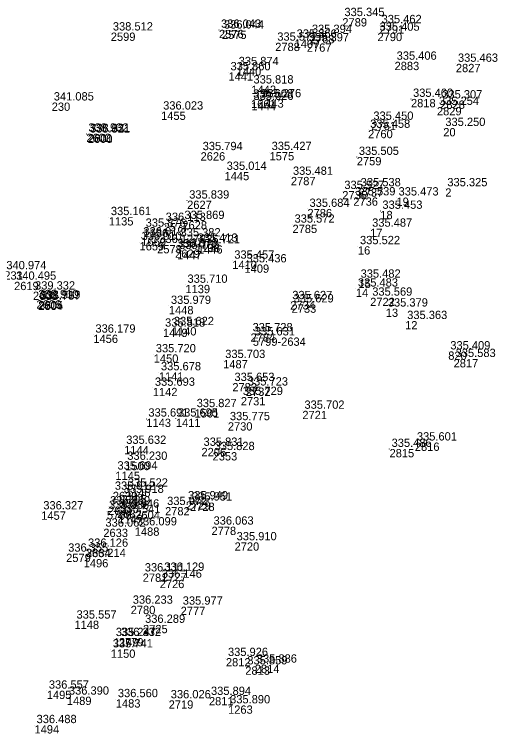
# Model space of a CAD drawing. Extents: x -829398 to -819400, y -1074439 to -1067977.
# Drawn here: x -819998.2 to -819929.2, y -1073325.7 to -1073221.6 of the extents above; entities that cross this region are included whole.
import ezdxf

# ---------------------------------------------------------------- set-up
doc = ezdxf.new("R2010")
doc.units = 0
for name, color, linetype in [('Vrstva 60', 7, 'Continuous'), ('Vrstva 61', 7, 'Continuous'), ('Čísla bodů_doměření_2012', 7, 'Continuous')]:
    doc.layers.add(name, color=color, linetype=linetype)

# ---------------------------------------------------------------- blocks, each defined once
blk = doc.blocks.new('BOD')
at = {"layer": 'Čísla bodů_doměření_2012'}
for p, q in [((-0.15, 0), (0.15, 0)), ((0, -0.15), (0, 0.15))]:
    blk.add_line(p, q, dxfattribs=at)

msp = doc.modelspace()

# ---------------------------------------------------------------- block references
at = {"layer": 'Vrstva 60', "xscale": 0.010000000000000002, "yscale": 0.010000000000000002}
for p in [(-819950.692, -1073222.135), (-819945.306, -1073223.158), (-819984.23, -1073224.218), (-819984.23, -1073224.218), (-819968.559, -1073223.823), (-819968.559, -1073223.823), (-819968.135, -1073223.939), (-819968.135, -1073223.939), (-819955.405, -1073224.574), (-819955.405, -1073224.574), (-819945.601, -1073224.25), (-819957.608, -1073225.257), (-819957.608, -1073225.257), (-819960.415, -1073225.694), (-819960.415, -1073225.694), (-819955.83, -1073225.792), (-819955.83, -1073225.792), (-819943.129, -1073228.449), (-819966.008, -1073229.234), (-819966.008, -1073229.234), (-819934.25, -1073228.748), (-819967.188, -1073229.98), (-819967.188, -1073229.98), (-819963.866, -1073231.888), (-819963.866, -1073231.888), (-819963.919, -1073233.941), (-819963.919, -1073233.941), (-819962.758, -1073233.88), (-819962.758, -1073233.88), (-819940.752, -1073233.821), (-819992.785, -1073234.345), (-819992.785, -1073234.345), (-819963.868, -1073234.268), (-819963.868, -1073234.268), (-819936.52, -1073234.049), (-819976.945, -1073235.658), (-819976.945, -1073235.658), (-819936.995, -1073234.992), (-819946.498, -1073237.14), (-819936.076, -1073238.036), (-819936.076, -1073238.036), (-819987.773, -1073238.853), (-819987.773, -1073238.853), (-819987.558, -1073238.989), (-819987.558, -1073238.989), (-819987.525, -1073238.907), (-819987.525, -1073238.907), (-819946.964, -1073238.306), (-819971.225, -1073241.531), (-819971.225, -1073241.531), (-819961.237, -1073241.513), (-819961.237, -1073241.513), (-819948.602, -1073242.224), (-819967.749, -1073244.384), (-819967.749, -1073244.384), (-819958.146, -1073245.103), (-819958.146, -1073245.103), (-819950.704, -1073247.152), (-819948.336, -1073246.762), (-819935.785, -1073246.762), (-819935.785, -1073246.762), (-819949.106, -1073248.075), (-819942.855, -1073248.093), (-819942.855, -1073248.093), (-819973.173, -1073248.54), (-819973.173, -1073248.54), (-819955.749, -1073249.74), (-819955.749, -1073249.74), (-819945.193, -1073250.02), (-819945.193, -1073250.02), (-819984.516, -1073250.932), (-819984.516, -1073250.932), (-819973.864, -1073251.491), (-819973.864, -1073251.491), (-819979.481, -1073252.611), (-819979.481, -1073252.611), (-819976.577, -1073251.772), (-819976.577, -1073251.772), (-819957.916, -1073252.023), (-819957.916, -1073252.023), (-819946.677, -1073252.611), (-819946.677, -1073252.611), (-819980.07, -1073254.537), (-819980.07, -1073254.537), (-819979.807, -1073253.866), (-819979.807, -1073253.866), (-819974.425, -1073254.013), (-819974.425, -1073254.013), (-819977.514, -1073254.962), (-819977.514, -1073254.962), (-819974.919, -1073255.604), (-819974.919, -1073255.604), (-819971.957, -1073254.785), (-819971.957, -1073254.785), (-819971.612, -1073254.996), (-819971.612, -1073254.996), (-819948.435, -1073255.14), (-819948.435, -1073255.14), (-819974.627, -1073255.838), (-819974.627, -1073255.838), (-819966.644, -1073257.234), (-819966.644, -1073257.234), (-819964.868, -1073257.772), (-819964.868, -1073257.772), (-819973.422, -1073260.725), (-819973.422, -1073260.725), (-819948.351, -1073259.986), (-819948.351, -1073259.986), (-819995.501, -1073261.703), (-819995.501, -1073261.703), (-819948.737, -1073261.273), (-819948.737, -1073261.273), (-819995.005, -1073262.947), (-819995.005, -1073262.947), (-819994.738, -1073263.045), (-819994.738, -1073263.045), (-819946.663, -1073262.588), (-819994.739, -1073263.171), (-819994.739, -1073263.171), (-819975.819, -1073263.78), (-819975.819, -1073263.78), (-819958.248, -1073263.095), (-819958.248, -1073263.095), (-819958.046, -1073263.564), (-819958.046, -1073263.564), (-819944.407, -1073264.163), (-819944.407, -1073264.163), (-819941.601, -1073265.968), (-819941.601, -1073265.968), (-819976.666, -1073267.072), (-819976.666, -1073267.072), (-819975.391, -1073266.849), (-819975.391, -1073266.849), (-819986.753, -1073267.935), (-819986.753, -1073267.935), (-819963.994, -1073267.746), (-819963.994, -1073267.746), (-819963.661, -1073268.341), (-819963.661, -1073268.341), (-819935.356, -1073270.365), (-819978.011, -1073270.786), (-819978.011, -1073270.786), (-819967.956, -1073271.609), (-819967.956, -1073271.609), (-819934.584, -1073271.465), (-819977.263, -1073273.386), (-819977.263, -1073273.386), (-819966.619, -1073274.934), (-819966.619, -1073274.934), (-819978.144, -1073275.627), (-819978.144, -1073275.627), (-819964.666, -1073275.589), (-819964.666, -1073275.589), (-819965.401, -1073276.96), (-819965.401, -1073276.96), (-819972.092, -1073278.717), (-819972.092, -1073278.717), (-819956.483, -1073278.954), (-819956.483, -1073278.954), (-819979.083, -1073280.087), (-819979.083, -1073280.087), (-819974.802, -1073280.085), (-819974.802, -1073280.085), (-819967.279, -1073280.605), (-819967.279, -1073280.605), (-819940.193, -1073283.546), (-819982.294, -1073284.03), (-819982.294, -1073284.03), (-819971.098, -1073284.317), (-819971.098, -1073284.317), (-819969.491, -1073284.931), (-819969.491, -1073284.931), (-819943.858, -1073284.474), (-819982.142, -1073286.341), (-819982.142, -1073286.341), (-819983.563, -1073287.746), (-819983.563, -1073287.746), (-819983.941, -1073290.67), (-819983.941, -1073290.67), (-819982.661, -1073291.124), (-819982.661, -1073291.124), (-819982.06, -1073290.213), (-819982.06, -1073290.213), (-819973.349, -1073292.054), (-819973.349, -1073292.054), (-819984.628, -1073292.803), (-819984.628, -1073292.803), (-819983.312, -1073293.252), (-819983.312, -1073293.252), (-819976.37, -1073292.878), (-819976.37, -1073292.878), (-819972.757, -1073292.236), (-819972.757, -1073292.236), (-819994.307, -1073293.514), (-819994.307, -1073293.514), (-819984.793, -1073293.449), (-819984.793, -1073293.449), (-819983.148, -1073294.05), (-819983.148, -1073294.05), (-819985.308, -1073296.01), (-819985.308, -1073296.01), (-819980.759, -1073295.829), (-819980.759, -1073295.829), (-819969.647, -1073295.718), (-819969.647, -1073295.718), (-819966.303, -1073297.985), (-819966.303, -1073297.985), (-819987.821, -1073298.922), (-819987.821, -1073298.922), (-819990.699, -1073299.63), (-819990.699, -1073299.63), (-819988.154, -1073300.4), (-819988.154, -1073300.4), (-819979.606, -1073302.491), (-819979.606, -1073302.491), (-819976.785, -1073302.394), (-819976.785, -1073302.394), (-819977.146, -1073303.403), (-819977.146, -1073303.403), (-819981.346, -1073307.163), (-819981.346, -1073307.163), (-819974.108, -1073307.299), (-819974.108, -1073307.299), (-819989.492, -1073309.317), (-819989.492, -1073309.317), (-819979.562, -1073309.929), (-819979.562, -1073309.929), (-819983.805, -1073311.843), (-819983.805, -1073311.843), (-819983.066, -1073311.831), (-819983.066, -1073311.831), (-819984.234, -1073313.485), (-819984.234, -1073313.485), (-819967.557, -1073314.727), (-819967.557, -1073314.727), (-819964.751, -1073315.942), (-819964.751, -1073315.942), (-819963.37, -1073315.686), (-819963.37, -1073315.686), (-819993.498, -1073319.45), (-819993.498, -1073319.45), (-819990.592, -1073320.315), (-819990.592, -1073320.315), (-819983.503, -1073320.685), (-819983.503, -1073320.685), (-819975.845, -1073320.85), (-819975.845, -1073320.85), (-819970.018, -1073320.363), (-819970.018, -1073320.363), (-819967.245, -1073321.581), (-819967.245, -1073321.581), (-819995.278, -1073324.44), (-819995.278, -1073324.44)]:
    msp.add_blockref('BOD', p, dxfattribs=at)

# ---------------------------------------------------------------- texts
at = {"layer": 'Vrstva 60'}
for s, p in [('2789', (-819950.692, -1073223.335)), ('2791', (-819945.306, -1073224.358)), ('2599', (-819984.23, -1073225.418)), ('2576', (-819968.559, -1073225.023)), ('2575', (-819968.135, -1073225.139)), ('2768', (-819955.405, -1073225.774)), ('2790', (-819945.601, -1073225.45)), ('1407', (-819957.608, -1073226.457)), ('2788', (-819960.415, -1073226.894)), ('2767', (-819955.83, -1073226.992)), ('2883', (-819943.129, -1073229.649)), ('2827', (-819934.25, -1073229.948)), ('1440', (-819966.008, -1073230.434)), ('1441', (-819967.188, -1073231.18)), ('1442', (-819963.866, -1073233.088)), ('1661', (-819963.919, -1073235.141)), ('1443', (-819962.758, -1073235.08)), ('2818', (-819940.752, -1073235.021)), ('230', (-819992.785, -1073235.545)), ('1444', (-819963.868, -1073235.468)), ('2829', (-819936.995, -1073236.192)), ('2828', (-819936.52, -1073235.249)), ('1455', (-819976.945, -1073236.858)), ('2761', (-819946.498, -1073238.34)), ('20', (-819936.076, -1073239.236)), ('2602', (-819987.773, -1073240.053)), ('2600', (-819987.558, -1073240.189)), ('2601', (-819987.525, -1073240.107)), ('2760', (-819946.964, -1073239.506)), ('2626', (-819971.225, -1073242.731)), ('1575', (-819961.237, -1073242.713)), ('2759', (-819948.602, -1073243.424)), ('1445', (-819967.749, -1073245.584)), ('2787', (-819958.146, -1073246.303)), ('2735', (-819950.704, -1073248.352)), ('2737', (-819948.336, -1073247.962)), ('2', (-819935.785, -1073247.962)), ('2736', (-819949.106, -1073249.275)), ('19', (-819942.855, -1073249.293)), ('2627', (-819973.173, -1073249.74)), ('2786', (-819955.749, -1073250.94)), ('18', (-819945.193, -1073251.22)), ('1135', (-819984.516, -1073252.132)), ('2628', (-819973.864, -1073252.691)), ('1136', (-819979.481, -1073253.811)), ('2577', (-819976.577, -1073252.972)), ('2785', (-819957.916, -1073253.223)), ('17', (-819946.677, -1073253.811)), ('1659', (-819980.07, -1073255.737)), ('1660', (-819979.807, -1073255.066)), ('1137', (-819974.425, -1073255.213)), ('2578', (-819977.514, -1073256.162)), ('2629', (-819974.919, -1073256.804)), ('1138', (-819971.957, -1073255.985)), ('1446', (-819971.612, -1073256.196)), ('16', (-819948.435, -1073256.34)), ('1447', (-819974.627, -1073257.038)), ('1410', (-819966.644, -1073258.434)), ('1409', (-819964.868, -1073258.972)), ('231', (-819999.654, -1073259.965)), ('2619', (-819998.236, -1073261.482)), ('1139', (-819973.422, -1073261.925)), ('15', (-819948.351, -1073261.186)), ('2603', (-819995.501, -1073262.903)), ('14', (-819948.737, -1073262.473)), ('2606', (-819995.005, -1073264.147)), ('2605', (-819994.738, -1073264.245)), ('2734', (-819958.248, -1073264.295)), ('2722', (-819946.663, -1073263.788)), ('2604', (-819994.739, -1073264.371)), ('1448', (-819975.819, -1073264.98)), ('2733', (-819958.046, -1073264.764)), ('13', (-819944.407, -1073265.363)), ('12', (-819941.601, -1073267.168)), ('1449', (-819976.666, -1073268.272)), ('1140', (-819975.391, -1073268.049)), ('1456', (-819986.753, -1073269.135)), ('2784', (-819963.994, -1073268.946)), ('5799-2634', (-819963.661, -1073269.541)), ('820', (-819935.356, -1073271.565)), ('1450', (-819978.011, -1073271.986)), ('1487', (-819967.956, -1073272.809)), ('2817', (-819934.584, -1073272.665)), ('1141', (-819977.263, -1073274.586)), ('2783', (-819966.619, -1073276.134)), ('1142', (-819978.144, -1073276.827)), ('2732', (-819964.666, -1073276.789)), ('2731', (-819965.401, -1073278.16)), ('1501', (-819972.092, -1073279.917)), ('2721', (-819956.483, -1073280.154)), ('1143', (-819979.083, -1073281.287)), ('1411', (-819974.802, -1073281.285)), ('2730', (-819967.279, -1073281.805)), ('2816', (-819940.193, -1073284.746)), ('1144', (-819982.294, -1073285.23)), ('2206', (-819971.098, -1073285.517)), ('2353', (-819969.491, -1073286.131)), ('2815', (-819943.858, -1073285.674)), ('1500', (-819982.142, -1073287.541)), ('1145', (-819983.563, -1073288.946)), ('2630', (-819983.941, -1073291.87)), ('2205', (-819982.661, -1073292.324)), ('1146', (-819982.06, -1073291.413)), ('2729', (-819973.349, -1073293.254)), ('2728', (-819972.757, -1073293.436)), ('2631', (-819984.628, -1073294.003)), ('2632', (-819983.312, -1073294.452)), ('2782', (-819976.37, -1073294.078)), ('1457', (-819994.307, -1073294.714)), ('5799-2604', (-819984.793, -1073294.649)), ('1147', (-819983.148, -1073295.25)), ('2633', (-819985.308, -1073297.21)), ('1488', (-819980.759, -1073297.029)), ('2778', (-819969.647, -1073296.918)), ('2720', (-819966.303, -1073299.185)), ('2634', (-819987.821, -1073300.122)), ('2579', (-819990.699, -1073300.83)), ('1496', (-819988.154, -1073301.6)), ('2781', (-819979.606, -1073303.691)), ('2727', (-819976.785, -1073303.594)), ('2726', (-819977.146, -1073304.603)), ('2780', (-819981.346, -1073308.363)), ('2777', (-819974.108, -1073308.499)), ('1148', (-819989.492, -1073310.517)), ('2725', (-819979.562, -1073311.129)), ('1149', (-819983.805, -1073313.043)), ('2779', (-819983.066, -1073313.031)), ('1150', (-819984.234, -1073314.685)), ('2812', (-819967.557, -1073315.927)), ('2813', (-819964.751, -1073317.142)), ('2814', (-819963.37, -1073316.886)), ('1495', (-819993.498, -1073320.65)), ('1489', (-819990.592, -1073321.515)), ('1483', (-819983.503, -1073321.885)), ('2719', (-819975.845, -1073322.05)), ('2811', (-819970.018, -1073321.563)), ('1263', (-819967.245, -1073322.781)), ('1494', (-819995.278, -1073325.64))]:
    msp.add_text(s, height=1.2, dxfattribs=at).set_placement(p)
at = {"layer": 'Vrstva 61'}
for s, p in [('335.345', (-819950.392, -1073221.835)), ('336.043', (-819968.259, -1073223.523)), ('336.044', (-819967.835, -1073223.639)), ('335.462', (-819945.006, -1073222.858)), ('338.512', (-819983.93, -1073223.918)), ('335.394', (-819955.105, -1073224.274)), ('335.405', (-819945.301, -1073223.95)), ('335.572', (-819960.115, -1073225.394)), ('335.366', (-819957.308, -1073224.957)), ('335.397', (-819955.53, -1073225.492)), ('335.406', (-819942.829, -1073228.149)), ('335.463', (-819933.95, -1073228.448)), ('335.860', (-819966.888, -1073229.68)), ('335.874', (-819965.708, -1073228.934)), ('335.818', (-819963.566, -1073231.588)), ('341.085', (-819992.485, -1073234.045)), ('335.608', (-819963.619, -1073233.641)), ('335.026', (-819963.568, -1073233.968)), ('335.276', (-819962.458, -1073233.58)), ('335.460', (-819940.452, -1073233.521)), ('335.307', (-819936.22, -1073233.749)), ('335.254', (-819936.695, -1073234.692)), ('336.023', (-819976.645, -1073235.358)), ('335.450', (-819946.198, -1073236.84)), ('335.458', (-819946.664, -1073238.006)), ('335.250', (-819935.776, -1073237.736)), ('338.932', (-819987.473, -1073238.553)), ('335.821', (-819987.258, -1073238.689)), ('338.931', (-819987.225, -1073238.607)), ('335.794', (-819970.925, -1073241.231)), ('335.427', (-819960.937, -1073241.213)), ('335.505', (-819948.302, -1073241.924)), ('335.014', (-819967.449, -1073244.084)), ('335.481', (-819957.846, -1073244.803)), ('335.538', (-819948.036, -1073246.462)), ('335.325', (-819935.485, -1073246.462)), ('335.527', (-819950.404, -1073246.852)), ('335.839', (-819972.873, -1073248.24)), ('335.539', (-819948.806, -1073247.775)), ('335.473', (-819942.555, -1073247.793)), ('335.684', (-819955.449, -1073249.44)), ('335.453', (-819944.893, -1073249.72)), ('335.161', (-819984.216, -1073250.632)), ('336.113', (-819976.277, -1073251.472)), ('335.869', (-819973.564, -1073251.191)), ('335.572', (-819957.616, -1073251.723)), ('335.876', (-819979.181, -1073252.311)), ('335.487', (-819946.377, -1073252.311)), ('336.013', (-819979.507, -1073253.566)), ('335.382', (-819974.125, -1073253.713)), ('336.010', (-819979.77, -1073254.237)), ('336.127', (-819977.214, -1073254.662)), ('335.413', (-819971.657, -1073254.485)), ('335.721', (-819971.312, -1073254.696)), ('335.522', (-819948.135, -1073254.84)), ('336.079', (-819974.619, -1073255.304)), ('335.753', (-819974.327, -1073255.538)), ('335.457', (-819966.344, -1073256.934)), ('335.436', (-819964.568, -1073257.472)), ('340.974', (-819999.354, -1073258.465)), ('340.495', (-819997.936, -1073259.982)), ('335.482', (-819948.051, -1073259.686)), ('335.710', (-819973.122, -1073260.425)), ('335.483', (-819948.437, -1073260.973)), ('339.332', (-819995.201, -1073261.403)), ('338.910', (-819994.705, -1073262.647)), ('335.787', (-819994.439, -1073262.871)), ('338.919', (-819994.438, -1073262.745)), ('335.627', (-819957.948, -1073262.795)), ('335.569', (-819946.363, -1073262.288)), ('335.979', (-819975.519, -1073263.48)), ('335.629', (-819957.746, -1073263.264)), ('335.379', (-819944.107, -1073263.863)), ('335.363', (-819941.301, -1073265.668)), ('335.818', (-819976.366, -1073266.772)), ('335.622', (-819975.091, -1073266.549)), ('336.179', (-819986.453, -1073267.635)), ('335.728', (-819963.694, -1073267.446)), ('335.631', (-819963.361, -1073268.041)), ('335.720', (-819977.711, -1073270.486)), ('335.409', (-819935.056, -1073270.065)), ('335.703', (-819967.656, -1073271.309)), ('335.583', (-819934.284, -1073271.165)), ('335.678', (-819976.963, -1073273.086)), ('335.653', (-819966.319, -1073274.634)), ('335.693', (-819977.844, -1073275.327)), ('335.723', (-819964.366, -1073275.289)), ('335.729', (-819965.101, -1073276.66)), ('335.827', (-819971.792, -1073278.417)), ('335.702', (-819956.183, -1073278.654)), ('335.691', (-819978.783, -1073279.787)), ('335.695', (-819974.502, -1073279.785)), ('335.775', (-819966.979, -1073280.305)), ('335.632', (-819981.994, -1073283.73)), ('335.831', (-819970.798, -1073284.017)), ('335.601', (-819939.893, -1073283.246)), ('335.828', (-819969.191, -1073284.631)), ('335.486', (-819943.558, -1073284.174)), ('336.230', (-819981.842, -1073286.041)), ('335.694', (-819983.263, -1073287.446)), ('335.522', (-819981.76, -1073289.913)), ('335.912', (-819983.641, -1073290.37)), ('335.918', (-819982.361, -1073290.824)), ('335.949', (-819973.049, -1073291.754)), ('335.951', (-819972.457, -1073291.936)), ('336.327', (-819994.007, -1073293.214)), ('335.986', (-819984.493, -1073293.149)), ('335.969', (-819984.328, -1073292.503)), ('335.946', (-819983.012, -1073292.952)), ('335.972', (-819976.07, -1073292.578)), ('335.541', (-819982.848, -1073293.75)), ('336.063', (-819969.347, -1073295.418)), ('336.062', (-819985.008, -1073295.71)), ('336.099', (-819980.459, -1073295.529)), ('336.126', (-819987.521, -1073298.622)), ('335.910', (-819966.003, -1073297.685)), ('336.355', (-819990.399, -1073299.33)), ('336.214', (-819987.854, -1073300.1)), ('336.111', (-819979.306, -1073302.191)), ('336.129', (-819976.485, -1073302.094)), ('336.146', (-819976.846, -1073303.103)), ('336.233', (-819981.046, -1073306.863)), ('335.977', (-819973.808, -1073306.999)), ('335.557', (-819989.192, -1073309.017)), ('336.289', (-819979.262, -1073309.629)), ('335.247', (-819983.505, -1073311.543)), ('336.332', (-819982.766, -1073311.531)), ('335.741', (-819983.934, -1073313.185)), ('335.926', (-819967.257, -1073314.427)), ('335.859', (-819964.451, -1073315.642)), ('335.886', (-819963.07, -1073315.386)), ('336.557', (-819993.198, -1073319.15)), ('336.390', (-819990.292, -1073320.015)), ('336.560', (-819983.203, -1073320.385)), ('335.894', (-819969.718, -1073320.063)), ('336.026', (-819975.545, -1073320.55)), ('335.890', (-819966.945, -1073321.281)), ('336.488', (-819994.978, -1073324.14))]:
    msp.add_text(s, height=1.2, dxfattribs=at).set_placement(p)

doc.saveas('drawing.dxf')
